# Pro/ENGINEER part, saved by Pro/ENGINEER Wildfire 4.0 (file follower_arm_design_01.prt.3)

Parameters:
  METRIC = "NO"

Other parameters: PITCH, DRILL_DIAMETER, THREAD_DIAMETER, THREADS_PER_INCH, THREAD_DEPTH, THREAD_LENGTH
